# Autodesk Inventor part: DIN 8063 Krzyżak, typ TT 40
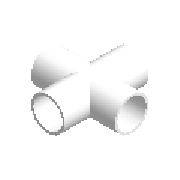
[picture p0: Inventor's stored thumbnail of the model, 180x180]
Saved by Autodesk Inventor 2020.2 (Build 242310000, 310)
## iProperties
Manager: www.cadconsulting.pl
Company: Fabian Stasiak CAD Consulting
NAME: PIPING: DIN 8063 Cross Type TT
DATA: <meta><inlinegroups number="2" deflen="4.6"></inlinegroups><connections number="4"></connections><angles><a>3.14159265358979</a><a>1.5707963267949</a><a>3.14159
Created: 2014-02
Part Number: DIN 8063 Krzyżak, typ TT 40
Material: PCW, nieplastyfikowany
Description: Krzyżak
Document SubType Name: Modeling
Standard: DIN 8063
Designer: F.Stasiak
Standards Organization: DIN
Language: pl-PL
Size Designation: 40
Categories: <MemberInstance><Categories><Category DisplayName="Rury cienko- i grubościenne" InternalName="4347fa0f-2144-441d-94cd-e3e15c92b736" Mnemonic="TUBEANDPIPE"><Cate
Density: 1.29 g/cm^3
Appearance: Gładki - biały
Catalog Web Link: www.expertbooks.pl
IsCustomPart: 0
Author: F.Stasiak
Subject: Zbiór ćwiczeń. Autodesk Inventor 2020. Kurs Professional
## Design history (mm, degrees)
sketch "Sketch1"
  geometry: L1 (0, 0)-(-94, 0); L2 (-94, 0)-(-94, 23); L3 (-94, 23)-(0, 23); L4 (0, 23)-(0, 0)
  constraints: 8 end point, 2 parallel, 1 horizontal, 1 perpendicular, 1 other
  dimensions: "d0" = 94 distance between parallel lines of L2 L4 (= 2 x z1 + 2 x t1); "d2" = 46 diameter of L3 L1 (= d1 + 2 x h1)
revolve "Revolve1" sketch "Sketch1" stored, may be unused: angle "d7" = 90 deg
sketch "Sketch2"
  geometry: L1 (0, -23)-(0, 23) reference; L2 (-94, -23)-(-94, 23) reference; L3 (0, 0)-(-94, 0); L4 (-47, 47)-(-47, -47); L5 (-47, 47)-(-24, 47); L6 (-24, 47)-(-24, -47); L7 (-24, -47)-(-47, -47); 1 further point
  constraints: 10 end point, 4 midpoint, 3 perpendicular, 1 parallel
  dimensions: "d3" = 94 distance between parallel lines of L7 L5 (= 2 x t1 + 2 x z1); "d4" = 46 diameter of L6 L4 (= d1 + 2 x h1)
revolve "Revolve2" sketch "Sketch2" stored, may be unused: angle "d25" = 90 deg
sketch "Sketch3"
  geometry: L1 (-70, 47)-(-24, 47) reference; L2 (-70, -47)-(-24, -47) reference; L3 (-47, -47)-(-47, 47); L4 (-27, 47)-(-27, 21); L5 (-27, 21)-(-31, 21); L6 (-31, 21)-(-31, -21); L7 (-31, -21)-(-27, -21); L8 (-27, -21)-(-27, -47)
  constraints: 12 end point, 3 parallel, 2 midpoint, 2 perpendicular, 2 point on line
  dimensions: "d5" = 32 diameter of L6 L3 (= 0.8 x d1); "d6" = 40 diameter of L8 L3 (= d1); "d8" = 40 diameter of L4 L3 (= d1); "d9" = 26 distance between parallel lines of L2 L7 (= t1); "d10" = 26 distance between parallel lines of L1 L5 (= t1)
revolve "Revolve3" sketch "Sketch3" stored, may be unused: angle "d32" = 90 deg
sketch "Sketch4"
  geometry: L1 (0, -23)-(0, 23) reference; L2 (-94, -23)-(-94, 23) reference; L3 (0, 0)-(-94, 0); L4 (0, 20)-(-26, 20); L5 (-26, 20)-(-26, 16); L6 (-26, 16)-(-68, 16); L7 (-68, 16)-(-68, 20); L8 (-68, 20)-(-94, 20)
  constraints: 12 end point, 3 parallel, 2 midpoint, 2 point on line, 1 collinear, 1 perpendicular
  dimensions: "d11" = 40 diameter of L4 L3 (= d1); "d12" = 40 diameter of L8 L3 (= d1); "d13" = 32 diameter of L6 L3 (= 0.8 x d1); "d14" = 26 distance between parallel lines of L2 L7 (= t1); "d15" = 26 distance between parallel lines of L1 L5 (= t1)
revolve "Revolve4" sketch "Sketch4" stored, may be unused: angle "d38" = 90 deg
workaxis "Work Axis1"
workpoint "Work Point1"
workpoint "Work Point2"
workaxis "Work Axis2"
workpoint "Work Point3"
workpoint "Work Point4"
workaxis "Work Axis3"
workpoint "Work Point5"
workpoint "Work Point6"
workaxis "Work Axis4"
workpoint "Work Point7"
workpoint "Work Point8"
body "Solid1"
other parameters: "d1" = 40 [user parameter; used in 8 equation terms], "z1" = 21 [user parameter; used in 2 equation terms], "t1" = 26 [user parameter; used in 6 equation terms], "h1" = 3 [user parameter; used in 2 equation terms]
